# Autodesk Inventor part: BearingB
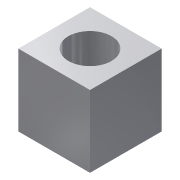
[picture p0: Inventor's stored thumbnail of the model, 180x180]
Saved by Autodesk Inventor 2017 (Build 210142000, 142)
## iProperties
Created: 2015-03
Part Number: BearingB
Document SubType Name: Modeling
Designer: Administrator
Density: 1 g/cm^3
Mass: 0.717257 g
Surface Area: 7.31947 cm^2
Volume: 0.717257 cm^3
Material: Generic
Appearance: Snow
Author: Administrator
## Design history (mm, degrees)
sketch "Sketch1"
  geometry: L1 (5, 5)-(5, -5); L2 (5, -5)-(-5, -5); L3 (-5, -5)-(-5, 5); L4 (-5, 5)-(5, 5); C1 r 3 at (0, 0); 1 further point
  constraints: 8 end point, 1 centre point, 1 coincident, 10 other
  dimensions: "d26" = 6 diameter of C1; "d27" = 10 distance of L3.end L1.start
extrude "Extrusion4" new body sketch "Sketch1" distance "d28" = 10; taper "d29" = 0 deg
body "Solid1"
